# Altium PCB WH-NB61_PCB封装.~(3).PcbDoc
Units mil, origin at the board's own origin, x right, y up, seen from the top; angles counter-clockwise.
Board outline 768.5 x 670.63 mil, 5 copper layers (L0, L1-Top Layer, L2, L3, L5); 1 components, 0 nets, 40 pads, 0 vias.
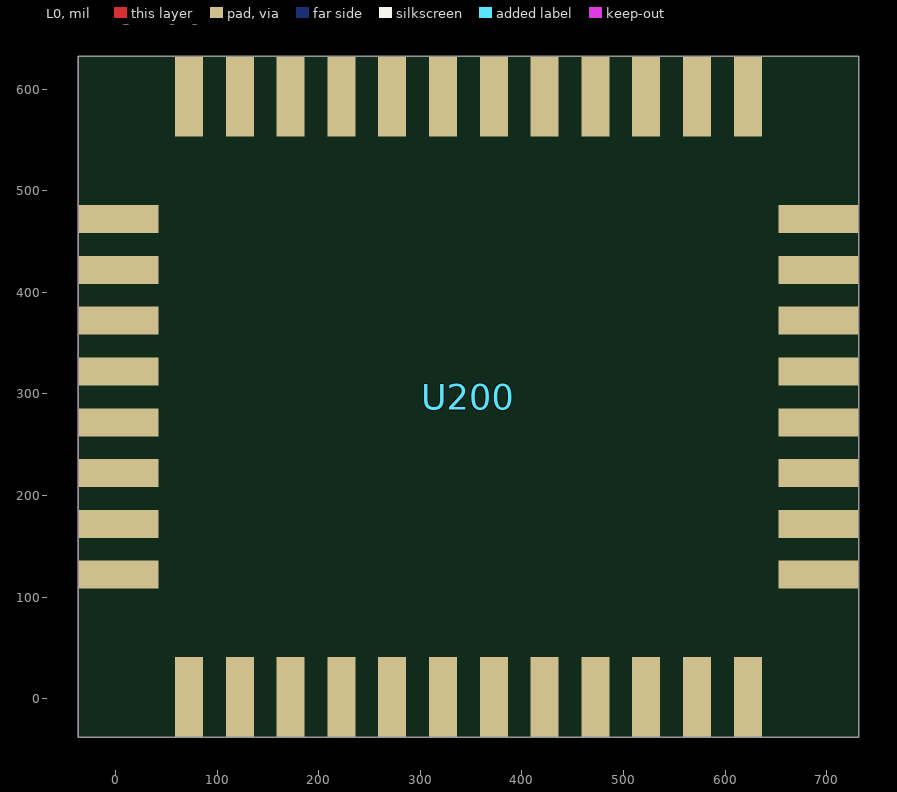
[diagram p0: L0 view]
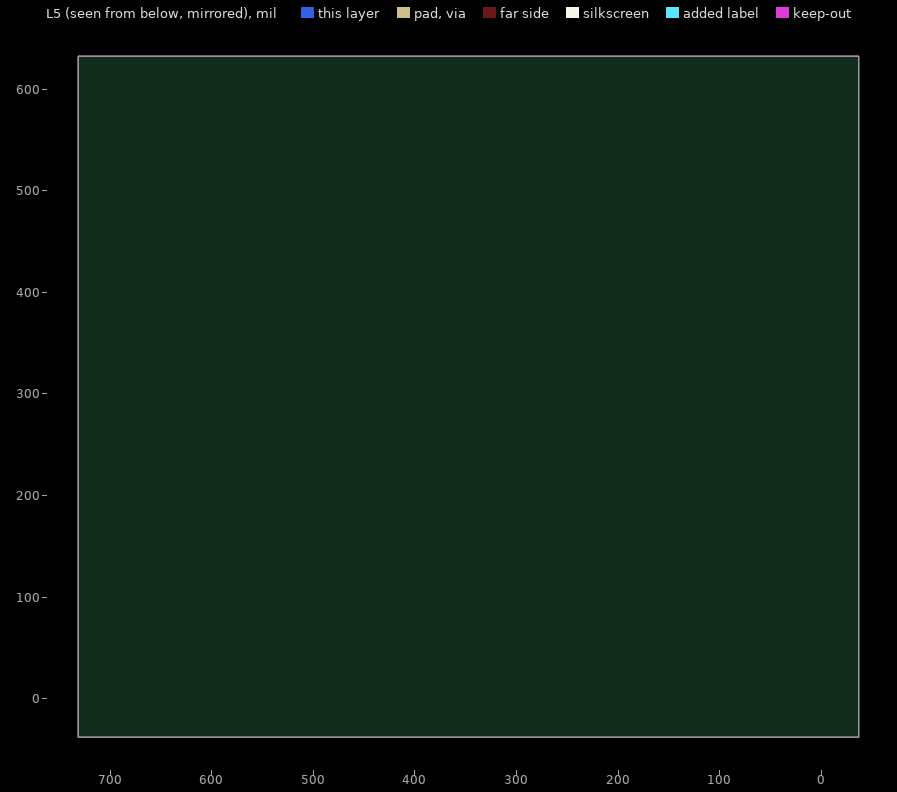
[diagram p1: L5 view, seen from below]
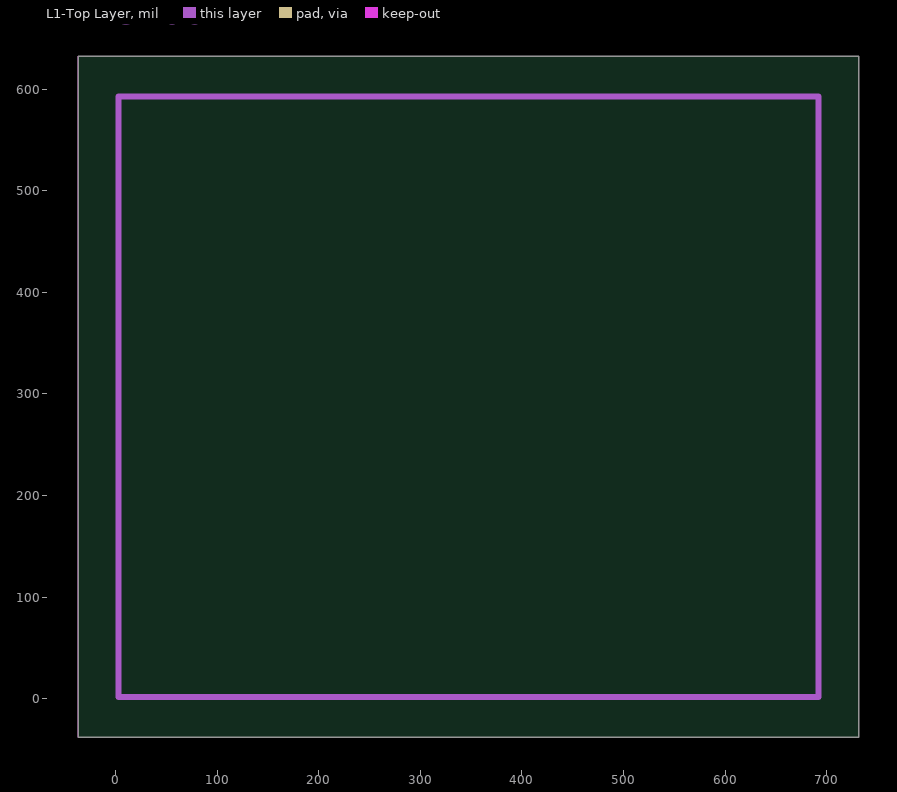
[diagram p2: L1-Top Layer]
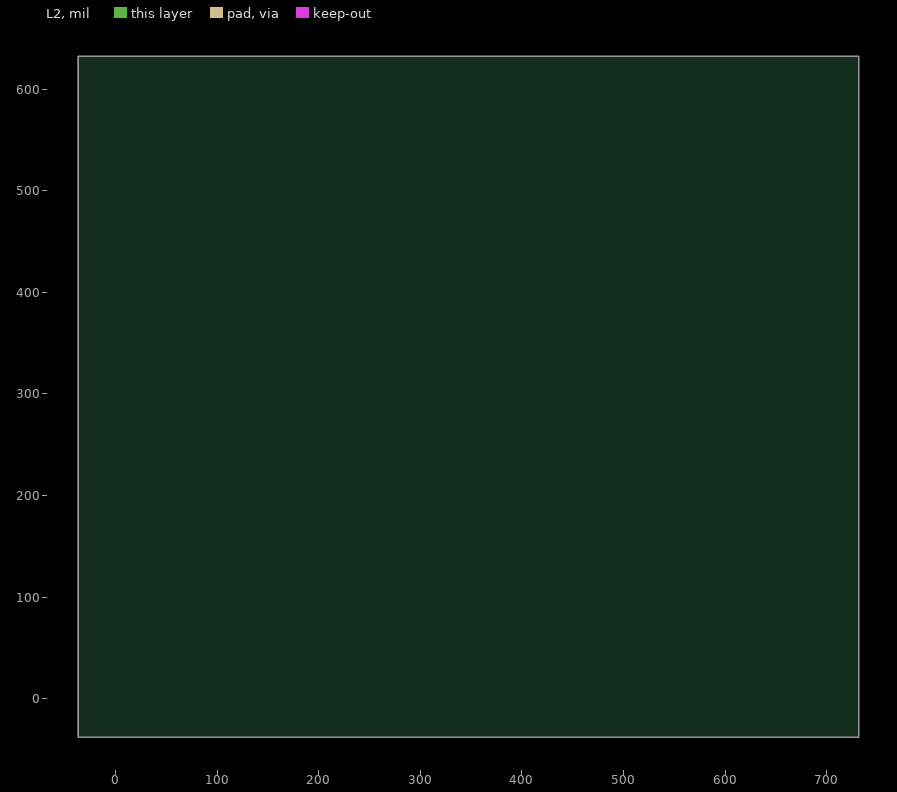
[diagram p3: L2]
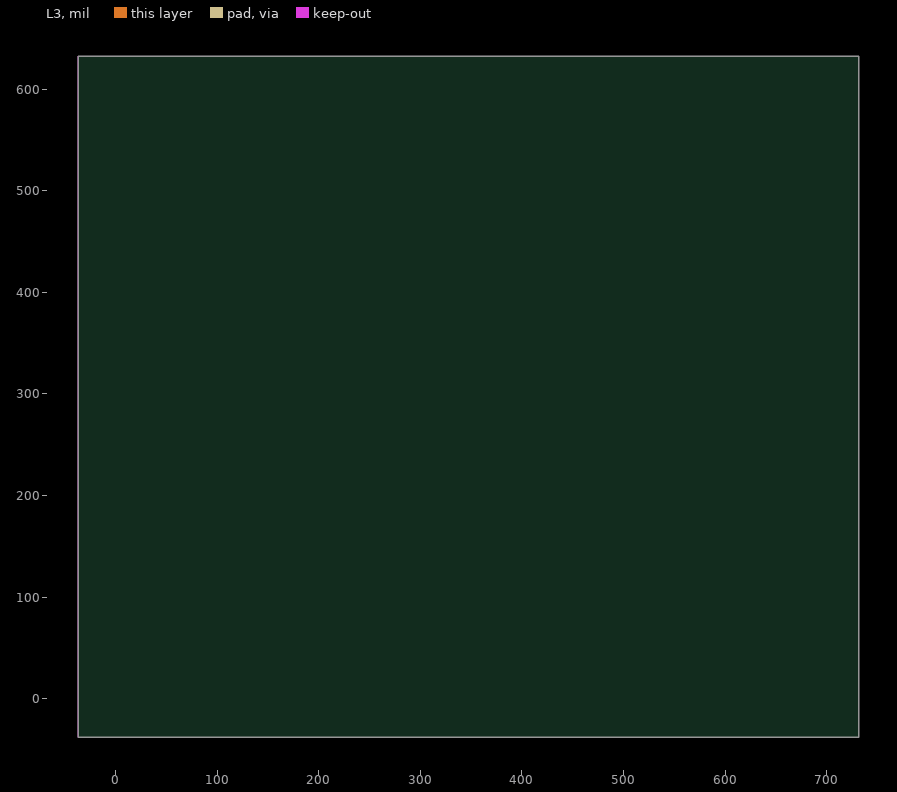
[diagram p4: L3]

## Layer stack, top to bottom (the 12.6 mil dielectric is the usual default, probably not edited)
L20 (Multiple PADS layers...): solder mask 0.4, Solder Resist, Dk 3.5
L0: signal copper 1.4
Dielectric 1: dielectric 12.6, FR-4, Dk 4.8
L1-Top Layer: signal copper 1.4
Dielectric2: dielectric 12.6, FR-4, Dk 4.8
L2: signal copper 1.4
Dielectric3: dielectric 12.6, FR-4, Dk 4.8
L3: signal copper 1.4
Dielectric4: dielectric 12.6, FR-4, Dk 4.8
L5: signal copper 1.4
L27-Assembly Drawing Top (Multiple PADS layers...): solder mask 0.4, Solder Resist, Dk 3.5

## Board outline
-36.93,632.49 731.57,632.49 731.57,-38.14 -36.93,-38.14

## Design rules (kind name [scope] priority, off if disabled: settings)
Clearance "Clearance - Default - DEFAULT- SMD" [IsVia vs IsSMTPin] p1: gap=0 ignorepadtopadclearanceinfootprint=FALSE
Clearance "Clearance - Default - DEFAULT - Via" [IsVia vs IsVia] p2: gap=0 ignorepadtopadclearanceinfootprint=FALSE
Clearance "Clearance - Default - DEFAULT - Net" [All] p3: gap=3 ignorepadtopadclearanceinfootprint=FALSE except(0: Arc-Hole Track-Hole SMDPad-Hole THPad-Hole Via-Hole Fill-Hole Poly-Hole Region-Hole Text-Hole; 3.94: SMDPad-Fill SMDPad-Poly SMDPad-Region THPad-Fill THPad-Poly THPad-Region Via-Fill Via-Poly Via-Region; 10: Text-Text)
ComponentClearance "ComponentClearance - Default - _1" [All] p1: gap=0 collisioncheckmode=3 verticalgap=10 showdistances=FALSE
ComponentClearance "ComponentClearance - Default - " [All] p2: gap=0 collisioncheckmode=3 verticalgap=10 showdistances=FALSE
ComponentClearance "ComponentClearance - Default - DEFAULT" [All] p3: gap=0 collisioncheckmode=3 verticalgap=10 showdistances=FALSE
FanoutControl Fanout_LCC [IsLCC] p1: bgadir=Out bgaviamode=Centered fanoutstyle=Auto fanoutdirection=Alternating viagrid=1 // Fanout_LCC (Default Rule)
FanoutControl Fanout_BGA [IsBGA] p2: bgadir=Out bgaviamode=Centered fanoutstyle=Auto fanoutdirection=Alternating viagrid=1 // Fanout_BGA (Default Rule)
FanoutControl Fanout_Small [(CompPinCount < 5)] p3: bgadir=Out bgaviamode=Centered fanoutstyle=Auto fanoutdirection=OutThenIn viagrid=1 // Fanout_Small (Default Rule)
FanoutControl Fanout_SOIC [IsSOIC] p4: bgadir=Out bgaviamode=Centered fanoutstyle=Auto fanoutdirection=Alternating viagrid=1 // Fanout_SOIC (Default Rule)
HoleToHoleClearance "HoleToHoleClearance - Default - DEFAULT" [All] p1: gap=0 allowstackedmicrovias=TRUE
Length "Default Length" [All] p1: maxlimit=50000 minlimit=0
MaxMinImpedance "Default Impedance" [All] p1: minimum=50.00 maximum=150.0
ParallelSegment "Default Parallel Segment Same Layer" [All] p1: limit=1000 gap=200
ParallelSegment "Default Parallel Segment Adjasent" [All] p2: limit=1000 gap=200
PlaneConnect "Default PlaneConnect" [All] p1: planeconnectstyle=Direct reliefexpansion=20 reliefentries=4 reliefconductorwidth=11.81 reliefairgap=10
PolygonConnect "PolygonConnect - Default SMT" [IsSMTPin] p1: connectstyle=Direct reliefconductorwidth=9.84 reliefentries=4 polygonreliefangle="45 Angle" airgapwidth=10
PolygonConnect "PolygonConnect - Default Pad" [All] p2: connectstyle=Direct reliefconductorwidth=11.81 reliefentries=4 polygonreliefangle="45 Angle" airgapwidth=10
RoutingLayers "RoutingLayers - Default - DEFAULT" [All] p1: top layer_v5=FALSE mid layer 1_v5=FALSE mid layer 2_v5=FALSE mid layer 3_v5=FALSE bottom layer_v5=FALSE
RoutingPriority "RoutingPriority - Default - DEFAULT" [All] p1: routingpriority=3
RoutingTopology "Default Routing Topology" [All] p1: topology=Shortest
SMDToCorner "SMDToCorner - Default - DEFAULT" [All] p1: distance=0
SolderMaskExpansion [All] p1: expansion=4
Width "Default Width" [All] p1: maxlimit=78.74 minlimit=3 preferedwidth=3.94
Width "Default Width_1" [All] p2: maxlimit=78.74 minlimit=2.99 preferedwidth=3
18 further rules are at their usual default settings.

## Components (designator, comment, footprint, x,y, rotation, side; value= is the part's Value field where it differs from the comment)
U200 "WH-NB61_I$2F$O" WH-NB61_I$2F$O 691.8,592.49 r0 top

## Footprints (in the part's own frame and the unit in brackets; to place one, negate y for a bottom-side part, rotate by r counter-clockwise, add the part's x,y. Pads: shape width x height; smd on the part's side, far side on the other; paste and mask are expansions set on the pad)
WH-NB61_I$2F$O [mm]
  rect 0.7x2 smd: 1(-1.765,0) 2(-3.035,0) 3(-4.305,0) 4(-5.575,0) 5(-6.845,0) 6(-8.115,0) 7(-9.385,0) 8(-10.655,0) 9(-11.925,0) 10(-13.195,0) 11(-14.465,0) 12(-15.735,0) 21(-15.735,-15.01) 22(-14.465,-15.01) 23(-13.195,-15.01) 24(-11.925,-15.01) 25(-10.655,-15.01) 26(-9.385,-15.01) 27(-8.115,-15.01) 28(-6.845,-15.01) 29(-5.575,-15.01) 30(-4.305,-15.01) 31(-3.035,-15.01) 32(-1.765,-15.01)
  rect 2x0.7 smd: 13(-17.5,-3.06) 14(-17.5,-4.33) 15(-17.5,-5.6) 16(-17.5,-6.87) 17(-17.5,-8.14) 18(-17.5,-9.41) 19(-17.5,-10.68) 20(-17.5,-11.95) 33(0,-11.95) 34(0,-10.68) 35(0,-9.41) 36(0,-8.14) 37(0,-6.87) 38(0,-5.6) 39(0,-4.33) 40(0,-3.06)
  L1-Top Layer lines w0.15: -17.5,-15.01 -17.5,0 0,0 0,-15.01 -17.5,-15.01

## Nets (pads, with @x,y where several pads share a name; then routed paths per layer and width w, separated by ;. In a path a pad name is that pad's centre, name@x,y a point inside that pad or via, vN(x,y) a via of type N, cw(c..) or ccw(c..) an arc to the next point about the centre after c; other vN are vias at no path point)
pads on no net: U200.1 U200.2 U200.3 U200.4 U200.5 U200.6 U200.7 U200.8 U200.9 U200.10 U200.11 U200.12 U200.13 U200.14 U200.15 U200.16 U200.17 U200.18 U200.19 U200.20 U200.21 U200.22 U200.23 U200.24 U200.25 U200.26 U200.27 U200.28 U200.29 U200.30 U200.31 U200.32 U200.33 U200.34 U200.35 U200.36 U200.37 U200.38 U200.39 U200.40

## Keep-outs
L2:
  region: 732.82,1073.36 819.46,1073.36 819.46,970.92 732.82,970.92 732.82,1073.36
Keep-Out Layer:
  the board outline again, w0.04

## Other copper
L2:
  region: 1074.64,1238.81 1040.75,1238.81 1030.45,1228.51 1030.45,1201.65 1035.6,1196.51 1043.53,1196.51 1057.03,1210 1074.84,1210 1079.09,1214.25 1079.09,1234.36 1074.64,1238.81
  region: 1282.89,725.76 1251.96,725.76 1251.96,698.2 1282.89,698.2 1282.89,725.76
  region: 971.36,851.59 986.92,851.59 990.96,855.64 990.96,875.39 984.01,882.35 975.12,882.35 967.26,874.49 967.26,855.7 971.36,851.59
  region: 1282.94,1225.76 1258.78,1225.76 1258.78,1198.2 1282.94,1198.2 1282.94,1225.76
  region: 1148.5,592.53 1176.09,592.53 1176.09,616.89 1148.5,616.89 1148.5,592.53
  region: 976.43,1158.73 957.32,1158.73 947.8,1149.21 947.8,1142.24 955.64,1134.41 981.82,1134.41 984.61,1137.2 984.61,1154.15 980,1158.76 976.43,1158.76 976.43,1158.73
  region: 998.44,592.39 1026.04,592.39 1026.04,622.68 998.44,622.68 998.44,592.39
  region: 762.49,996.64 743.56,996.64 737.38,990.47 737.38,984.41 743.29,978.5 762.74,978.5 764.68,980.44 764.68,994.45 762.49,996.64
  region: 1282.77,1125.76 1256.67,1125.76 1256.67,1098.22 1282.77,1098.22 1282.77,1125.76
  region: 1048.49,592.49 1076.1,592.49 1076.1,621.97 1048.49,621.97 1048.49,592.49
  region: 1282.74,1075.76 1254.96,1075.76 1254.96,1048.2 1282.74,1048.2 1282.74,1075.76
L3:
  region: 1282.64,1075.76 1255.94,1075.76 1255.94,1048.2 1282.64,1048.2 1282.64,1075.76
  region: 1148.49,592.48 1176.08,592.48 1176.08,619 1148.49,619 1148.49,592.48
  region: 1282.56,1125.77 1256.33,1125.77 1256.33,1098.22 1282.56,1098.22 1282.56,1125.77
  region: 998.48,592.49 1026.14,592.49 1026.14,621.25 998.48,621.25 998.48,592.49
  region: 1282.76,725.76 1256.12,725.76 1256.12,698.22 1282.76,698.22 1282.76,725.76
  region: 1048.5,592.45 1076.12,592.45 1076.12,624.07 1048.5,624.07 1048.5,592.45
